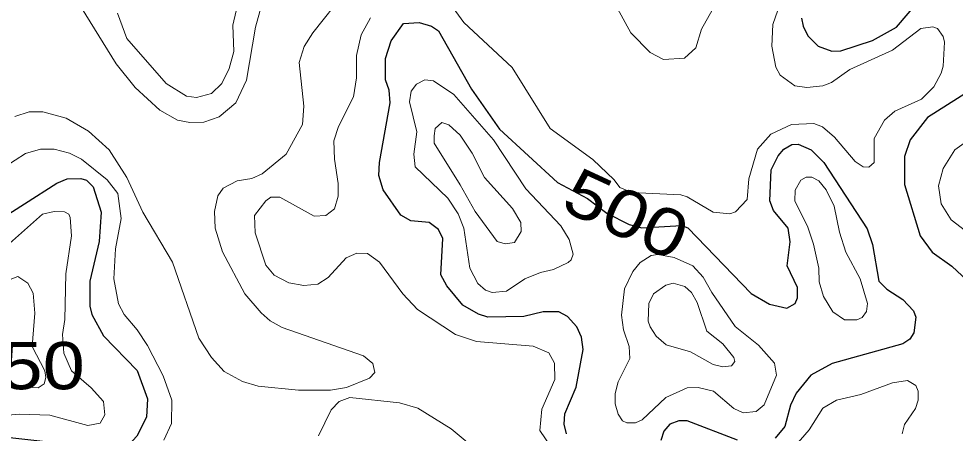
# Model space of a CAD drawing. Extents: x 577 to 602.9, y 7483.8 to 7511.6.
# Drawn here: x 581.887 to 583.474, y 7499.006 to 7499.708 of the extents above; entities that cross this region are included whole.
import ezdxf
from ezdxf.enums import TextEntityAlignment as Align

# ---------------------------------------------------------------- set-up
doc = ezdxf.new("R2010")
doc.units = 0
doc.header["$LTSCALE"] = 0.032
doc.layers.add('1', color=7, linetype='Continuous', lineweight=25)
doc.layers.add('2', color=7, linetype='Continuous', lineweight=13)
doc.layers.add('61', color=7, linetype='Continuous')

msp = doc.modelspace()

# ---------------------------------------------------------------- linework, layer by layer
at = {"layer": '1'}
for points in [[(583.213, 7499.7087), (583.2161, 7499.6952), (583.2241, 7499.6793), (583.2416, 7499.6618), (583.2647, 7499.6531), (583.2798, 7499.6539), (583.3338, 7499.6714), (583.3744, 7499.6936), (583.4269, 7499.7557)], [(582.8154, 7499.005), (582.8114, 7499.0217), (582.8122, 7499.0392), (582.8313, 7499.0845), (582.8432, 7499.1481), (582.8408, 7499.1688), (582.8329, 7499.1863), (582.817, 7499.2038), (582.8019, 7499.2118), (582.7756, 7499.2118), (582.743, 7499.2038), (582.6818, 7499.203), (582.6659, 7499.2078), (582.6396, 7499.2229), (582.6126, 7499.2555), (582.6023, 7499.2746), (582.6055, 7499.3358), (582.5983, 7499.3509), (582.5824, 7499.3628), (582.5514, 7499.366), (582.5347, 7499.3756), (582.5045, 7499.4185), (582.4973, 7499.4424), (582.4981, 7499.4646), (582.5164, 7499.5656), (582.5148, 7499.5871), (582.5084, 7499.6046), (582.5084, 7499.6404), (582.518, 7499.6706), (582.5387, 7499.7), (582.5657, 7499.7016), (582.5864, 7499.6952), (582.5983, 7499.6873), (582.654, 7499.5887), (582.7017, 7499.5211), (582.7999, 7499.4308), (582.8506, 7499.4038), (582.8832, 7499.379), (582.9215, 7499.3598), (582.9429, 7499.3542), (583.0102, 7499.3581), (583.0205, 7499.3541), (583.1279, 7499.2428), (583.1589, 7499.2245), (583.1883, 7499.2181), (583.2026, 7499.2261), (583.2066, 7499.2356), (583.2066, 7499.2531), (583.1891, 7499.2897), (583.1939, 7499.3302), (583.1907, 7499.3533), (583.1661, 7499.3835), (583.1597, 7499.3994), (583.1621, 7499.4519), (583.174, 7499.4758), (583.1835, 7499.4869), (583.1971, 7499.4948), (583.2074, 7499.4956), (583.2297, 7499.4861), (583.2511, 7499.4646), (583.3243, 7499.3525), (583.3338, 7499.3255), (583.3442, 7499.2634), (583.3577, 7499.2499), (583.3847, 7499.2324), (583.403, 7499.2133), (583.407, 7499.203), (583.4038, 7499.176), (583.3967, 7499.1656), (583.3847, 7499.1577), (583.2654, 7499.1243), (583.2289, 7499.1044), (583.2042, 7499.0742), (583.1947, 7499.0535), (583.1851, 7499.0177), (583.1684, 7498.9979)], [(583.4945, 7499.5839), (583.4269, 7499.541), (583.3974, 7499.5028), (583.3879, 7499.475), (583.3879, 7499.4272), (583.4141, 7499.3406), (583.4348, 7499.3127), (583.4682, 7499.2889), (583.4937, 7499.265)], [(581.8413, 7499.3597), (581.9518, 7499.4296), (581.9693, 7499.4368), (581.9924, 7499.4376), (582.0019, 7499.4344), (582.013, 7499.4233), (582.0266, 7499.3803), (582.0234, 7499.331), (582.0075, 7499.2634), (582.0075, 7499.2213), (582.0107, 7499.207), (582.0305, 7499.1712), (582.0878, 7499.1124), (582.1053, 7499.0646), (582.1037, 7499.0336), (582.087, 7499.001), (582.0735, 7498.9867), (582.0521, 7498.9759), (581.9916, 7498.9772), (581.9478, 7498.9899), (581.8517, 7499.0006)], [(583.1048, 7498.9947), (583.0197, 7499.0273), (583.0054, 7499.0273), (582.9903, 7499.0217), (582.98, 7499.0098), (582.9752, 7498.9939)]]:
    msp.add_lwpolyline(points, dxfattribs=at)
at = {"layer": '2'}
for points in [[(582.2691, 7499.7803), (582.25, 7499.6968), (582.2516, 7499.6523), (582.2436, 7499.6237), (582.2309, 7499.5982), (582.2134, 7499.5815), (582.188, 7499.5744), (582.1713, 7499.5767), (582.1371, 7499.5982), (582.0703, 7499.6745), (582.0544, 7499.7175)], [(582.6142, 7499.739), (582.6412, 7499.7016), (582.7231, 7499.6252), (582.7875, 7499.5219), (582.8599, 7499.4694), (582.8961, 7499.435), (582.9055, 7499.4223), (582.9259, 7499.4139), (583.0087, 7499.41), (583.0197, 7499.4066), (583.0635, 7499.3803), (583.0921, 7499.3779), (583.1016, 7499.3811), (583.1215, 7499.4018), (583.1239, 7499.4368), (583.139, 7499.4869), (583.1613, 7499.5123), (583.1963, 7499.529), (583.2344, 7499.5306), (583.2487, 7499.5251), (583.2694, 7499.5076), (583.3044, 7499.4662), (583.3179, 7499.4575), (583.3275, 7499.4567), (583.3362, 7499.4646), (583.3362, 7499.5052), (583.3537, 7499.5362), (583.3712, 7499.5513), (583.4165, 7499.572), (583.4372, 7499.5926), (583.4499, 7499.6157), (583.4531, 7499.6276), (583.4555, 7499.6682), (583.4531, 7499.6777), (583.4436, 7499.6912), (583.4356, 7499.6944), (583.4157, 7499.6912), (583.3672, 7499.6547), (583.2949, 7499.6221), (583.2639, 7499.5998), (583.2495, 7499.5942), (583.2225, 7499.5918), (583.2018, 7499.5942), (583.1772, 7499.6125), (583.17, 7499.626), (583.1629, 7499.6618), (583.1645, 7499.6984), (583.1899, 7499.7716)], [(582.4401, 7499.7533), (582.3852, 7499.6841), (582.3709, 7499.661), (582.3621, 7499.634), (582.3701, 7499.56), (582.3677, 7499.529), (582.3399, 7499.4789), (582.2993, 7499.4455), (582.2818, 7499.4376), (582.2572, 7499.4336), (582.2333, 7499.4209), (582.2246, 7499.4082), (582.219, 7499.3819), (582.2198, 7499.3533), (582.2325, 7499.3135), (582.2699, 7499.242), (582.2977, 7499.2102), (582.3128, 7499.1966), (582.3335, 7499.1855), (582.4711, 7499.137), (582.487, 7499.1243), (582.4902, 7499.1092), (582.4814, 7499.0996), (582.4424, 7499.0837), (582.4154, 7499.079), (582.3613, 7499.079), (582.2929, 7499.0861)], [(581.986, 7499.7382), (582.052, 7499.6316), (582.0846, 7499.5918), (582.126, 7499.5529), (582.1562, 7499.5362), (582.1769, 7499.5322), (582.2007, 7499.533), (582.2269, 7499.5418), (582.2548, 7499.5656), (582.2731, 7499.6038), (582.2882, 7499.6936), (582.2985, 7499.7302)], [(583.0722, 7499.7413), (583.0436, 7499.6904), (583.0341, 7499.6586), (583.015, 7499.6411), (582.9792, 7499.6388), (582.9569, 7499.6507), (582.9243, 7499.6841), (582.9013, 7499.7254)], [(582.4114, 7499.2698), (582.3939, 7499.2587), (582.3701, 7499.2563), (582.3446, 7499.2611), (582.32, 7499.2738), (582.3057, 7499.2905), (582.2874, 7499.3453), (582.2866, 7499.3748), (582.3057, 7499.3994), (582.3144, 7499.4058), (582.3295, 7499.4058), (582.3876, 7499.374), (582.4075, 7499.3748), (582.4218, 7499.3859), (582.4281, 7499.4074), (582.4281, 7499.4288), (582.4218, 7499.4702), (582.421, 7499.5012), (582.4289, 7499.5258), (582.4544, 7499.5759), (582.4591, 7499.6078), (582.4591, 7499.6459), (582.4671, 7499.6809), (582.483, 7499.7095)], [(582.2929, 7499.0861), (582.2659, 7499.0941), (582.2349, 7499.1108), (582.2134, 7499.1346), (582.192, 7499.1672), (582.1474, 7499.296), (582.0973, 7499.3803), (582.0703, 7499.4392), (582.0401, 7499.4861), (582.0051, 7499.5179), (581.9677, 7499.5394), (581.928, 7499.5505), (581.9049, 7499.5505), (581.8803, 7499.5425)], [(583.473, 7499.4861), (583.5279, 7499.5251)], [(581.8636, 7499.4575), (581.8985, 7499.4797), (581.924, 7499.4869), (581.947, 7499.4869), (581.9733, 7499.4805), (581.9932, 7499.4702), (582.0369, 7499.4352), (582.0552, 7499.4121), (582.0608, 7499.37), (582.0512, 7499.3183), (582.048, 7499.2674), (582.056, 7499.2253), (582.0655, 7499.207), (582.0878, 7499.1815), (582.1053, 7499.1545), (582.1315, 7499.1036), (582.1466, 7499.0623), (582.1458, 7499.0225), (582.1331, 7498.9947)], [(583.4499, 7499.3946), (583.4452, 7499.4249), (583.4531, 7499.4543), (583.473, 7499.4861)], [(583.5056, 7499.3374), (583.4666, 7499.3676), (583.4499, 7499.3946)], [(581.8684, 7499.0369), (581.889, 7499.0384), (581.9399, 7499.0368), (582.0043, 7499.0193), (582.025, 7499.0233), (582.0329, 7499.0376), (582.0305, 7499.0599), (582.0099, 7499.0829), (581.9765, 7499.1116), (581.9637, 7499.1418), (581.9614, 7499.1736), (581.9653, 7499.199), (581.9669, 7499.2762), (581.9765, 7499.3406), (581.9741, 7499.3716), (581.9717, 7499.3772), (581.9645, 7499.3811), (581.947, 7499.3819), (581.9272, 7499.3772), (581.8612, 7499.3183)], [(582.7987, 7498.9684), (582.7701, 7499.0106), (582.7732, 7499.0472), (582.7955, 7499.0972), (582.7947, 7499.1251), (582.7852, 7499.1426), (582.7589, 7499.1537), (582.6627, 7499.1617), (582.6269, 7499.1736), (582.5625, 7499.2157), (582.5379, 7499.242), (582.4981, 7499.296), (582.4782, 7499.3104), (582.4599, 7499.3112), (582.4416, 7499.3032), (582.4114, 7499.2698)], [(583.3839, 7499.005), (583.3879, 7499.0209), (583.4062, 7499.0479), (583.411, 7499.0623), (583.411, 7499.0774), (583.407, 7499.0869), (583.3927, 7499.0957), (583.3672, 7499.0917), (583.314, 7499.0718), (583.2726, 7499.0623), (583.2495, 7499.0487), (583.2265, 7499.0122), (583.2002, 7498.9819)], [(582.3947, 7499.0018), (582.4162, 7499.0456), (582.4297, 7499.0599), (582.448, 7499.067), (582.5323, 7499.0575), (582.5633, 7499.0487), (582.6198, 7499.0138), (582.65, 7498.9883)]]:
    msp.add_lwpolyline(points, dxfattribs=at)
for points in [[(582.6913, 7499.5028), (582.7462, 7499.4201), (582.8058, 7499.3573), (582.8194, 7499.3342), (582.8265, 7499.3096), (582.8233, 7499.3), (582.8178, 7499.2952), (582.7931, 7499.2833), (582.7708, 7499.2785), (582.7446, 7499.2674), (582.7136, 7499.2467), (582.6889, 7499.2444), (582.6778, 7499.2483), (582.6651, 7499.2595), (582.6516, 7499.2857), (582.6412, 7499.3533), (582.6317, 7499.3779), (582.6142, 7499.4042), (582.5585, 7499.4575), (582.5562, 7499.4789), (582.5617, 7499.5163), (582.549, 7499.5672), (582.5522, 7499.5855), (582.5609, 7499.5974), (582.5752, 7499.6046), (582.5895, 7499.603), (582.6245, 7499.5799)], [(582.6349, 7499.4265), (582.6603, 7499.3819), (582.6977, 7499.331), (582.7112, 7499.3271), (582.7271, 7499.3294), (582.7382, 7499.3477), (582.7375, 7499.3628), (582.7239, 7499.3867), (582.6762, 7499.4392), (582.6555, 7499.4805), (582.6349, 7499.5107), (582.6158, 7499.5282), (582.6039, 7499.5322), (582.5927, 7499.5219), (582.5908, 7499.5096), (582.5911, 7499.4972)], [(583.2774, 7499.3469), (583.2885, 7499.3127), (583.3124, 7499.2674), (583.3251, 7499.2261), (583.3235, 7499.2125), (583.3163, 7499.2022), (583.3068, 7499.1982), (583.2861, 7499.1982), (583.2662, 7499.2118), (583.2503, 7499.238), (583.2432, 7499.2626), (583.2424, 7499.2857), (583.2336, 7499.3263), (583.2241, 7499.3549), (583.2018, 7499.3994), (583.2026, 7499.4177), (583.2122, 7499.4344), (583.2209, 7499.44), (583.2305, 7499.44), (583.2424, 7499.4336), (583.2551, 7499.4185), (583.2686, 7499.3907)], [(583.0611, 7499.2444), (583.1008, 7499.1871), (583.1406, 7499.1553), (583.1676, 7499.1251), (583.1708, 7499.1044), (583.1501, 7499.0543), (583.1366, 7499.0432), (583.1144, 7499.0408), (583.0985, 7499.0479), (583.0643, 7499.0774), (583.038, 7499.0837), (583.0197, 7499.0829), (582.9832, 7499.067), (582.9434, 7499.0289), (582.9323, 7499.0241), (582.9172, 7499.0241), (582.91, 7499.0273), (582.9028, 7499.0384), (582.8973, 7499.0559), (582.8973, 7499.0734), (582.9028, 7499.0933), (582.9227, 7499.133), (582.9211, 7499.1529), (582.9116, 7499.1815), (582.9084, 7499.2062), (582.9132, 7499.2507), (582.9275, 7499.2801), (582.9402, 7499.2952), (582.9585, 7499.3072), (582.9696, 7499.3088), (582.9975, 7499.304), (583.0293, 7499.2897), (583.0468, 7499.2706)], [(581.8484, 7499.0869), (581.8238, 7499.0917), (581.8111, 7499.11), (581.8015, 7499.141), (581.8015, 7499.164), (581.8095, 7499.1871), (581.8556, 7499.2523), (581.8723, 7499.2666), (581.8858, 7499.2714), (581.9025, 7499.2603), (581.9113, 7499.2436), (581.9144, 7499.2094), (581.9097, 7499.1529), (581.9311, 7499.1116), (581.9327, 7499.1004), (581.9303, 7499.0901), (581.92, 7499.0829)], [(583.0364, 7499.2277), (583.0531, 7499.1792), (583.0802, 7499.1577), (583.0985, 7499.1346), (583.1001, 7499.1275), (583.0945, 7499.1203), (583.0802, 7499.1187), (583.0635, 7499.1227), (583.0253, 7499.1442), (582.984, 7499.1561), (582.9673, 7499.1704), (582.9569, 7499.1863), (582.9537, 7499.1959), (582.9545, 7499.2261), (582.9625, 7499.242), (582.9832, 7499.2571), (582.9959, 7499.2603), (583.0158, 7499.2547), (583.0269, 7499.2444)]]:
    msp.add_lwpolyline(points, close=True, dxfattribs=at)

# ---------------------------------------------------------------- texts
at = {"layer": '61', "width": 1.2}
msp.add_text('500', height=0.08, rotation=335.287, dxfattribs=at).set_placement((582.8997, 7499.3412), align=Align.CENTER)
msp.add_text('550', height=0.08, dxfattribs=at).set_placement((581.8919, 7499.0807), align=Align.CENTER)

doc.saveas('drawing.dxf')
